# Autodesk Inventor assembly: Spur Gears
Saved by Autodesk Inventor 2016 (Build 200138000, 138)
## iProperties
Created: 2015-08
Part Number: Spur Gears
Document SubType Name: Assembly
Designer: Ugljesa
Categories: <?xml version="1.0" encoding="UTF-16"?> <MemberInstance><Categories><FamilyTemplate/><ParamToTemplateMap><ParamToTemplate><ParamToTemplate CategoryParameter="//
Mass: 1344.39 g
Surface Area: 329.177 cm^2
Volume: 171.26 cm^3
Density: 7.85 g/cm^3
ClientObjectVersion: 1
Author: Ugljesa
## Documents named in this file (2)
- C:\Users\Ugljesa\Desktop\Turbokompr\Sklop turbokompresora\Design Accelerator\Spur Gears1.iam
- C:\Users\Ugljesa\Desktop\Turbokompr\Sklop turbokompresora\Design Accelerator\Spur Gear11.ipt
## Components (1 placed, 1 different names)
1. Spur Gear1:1
